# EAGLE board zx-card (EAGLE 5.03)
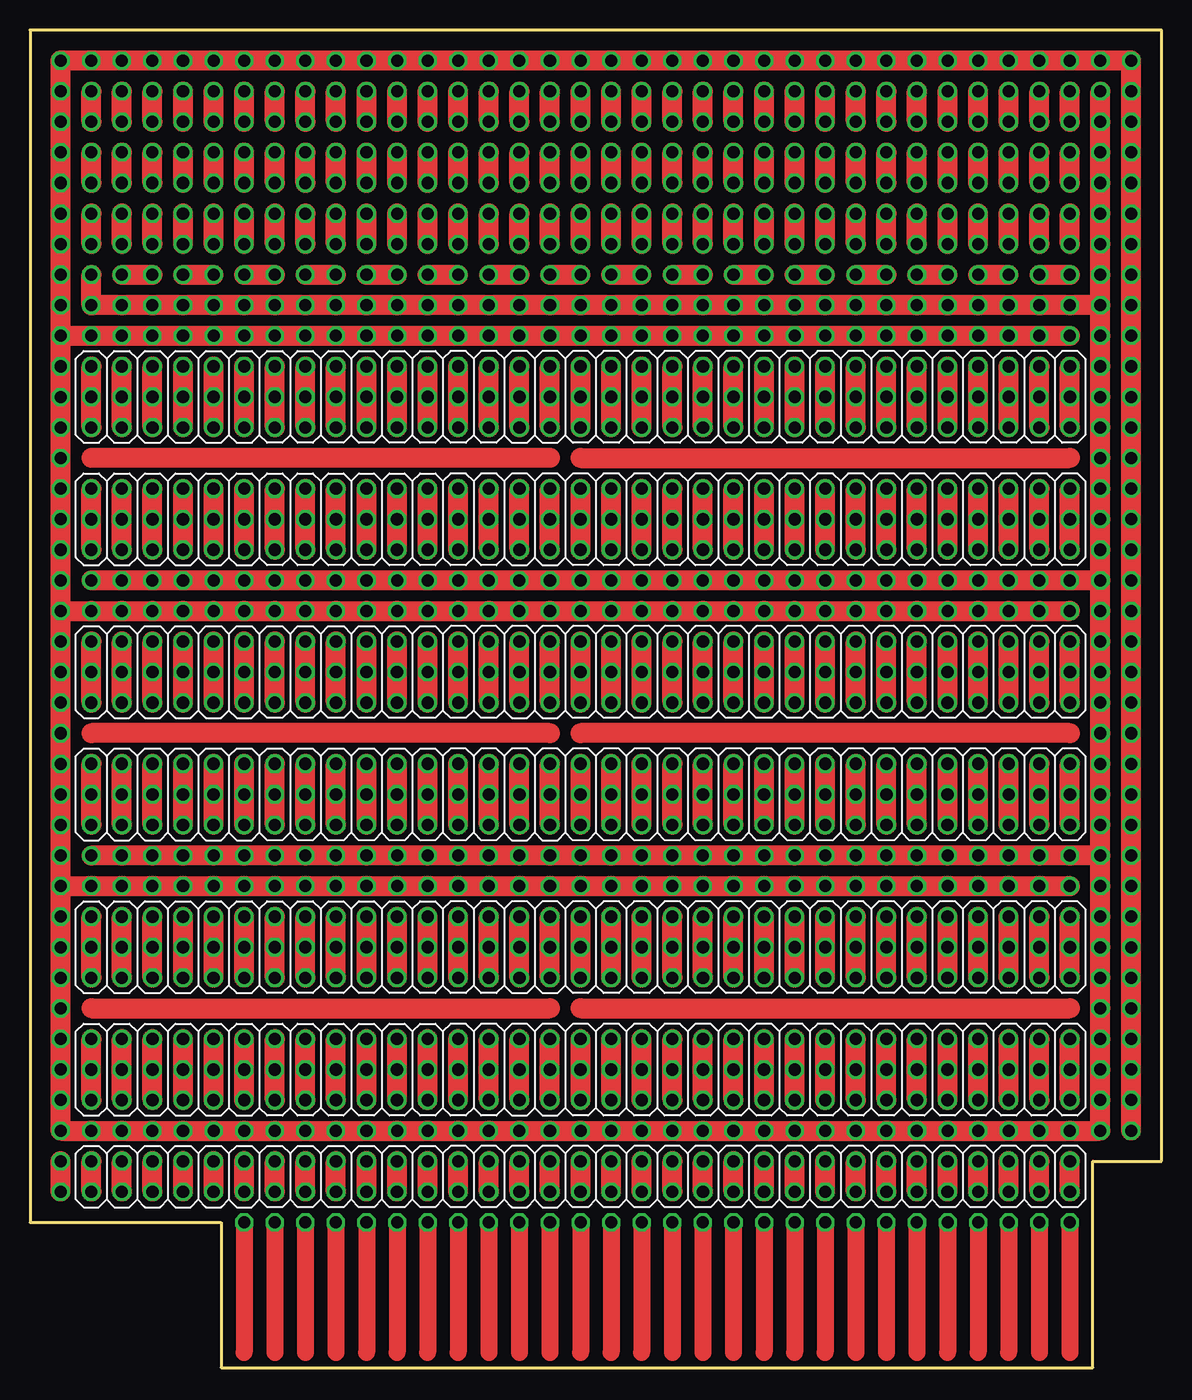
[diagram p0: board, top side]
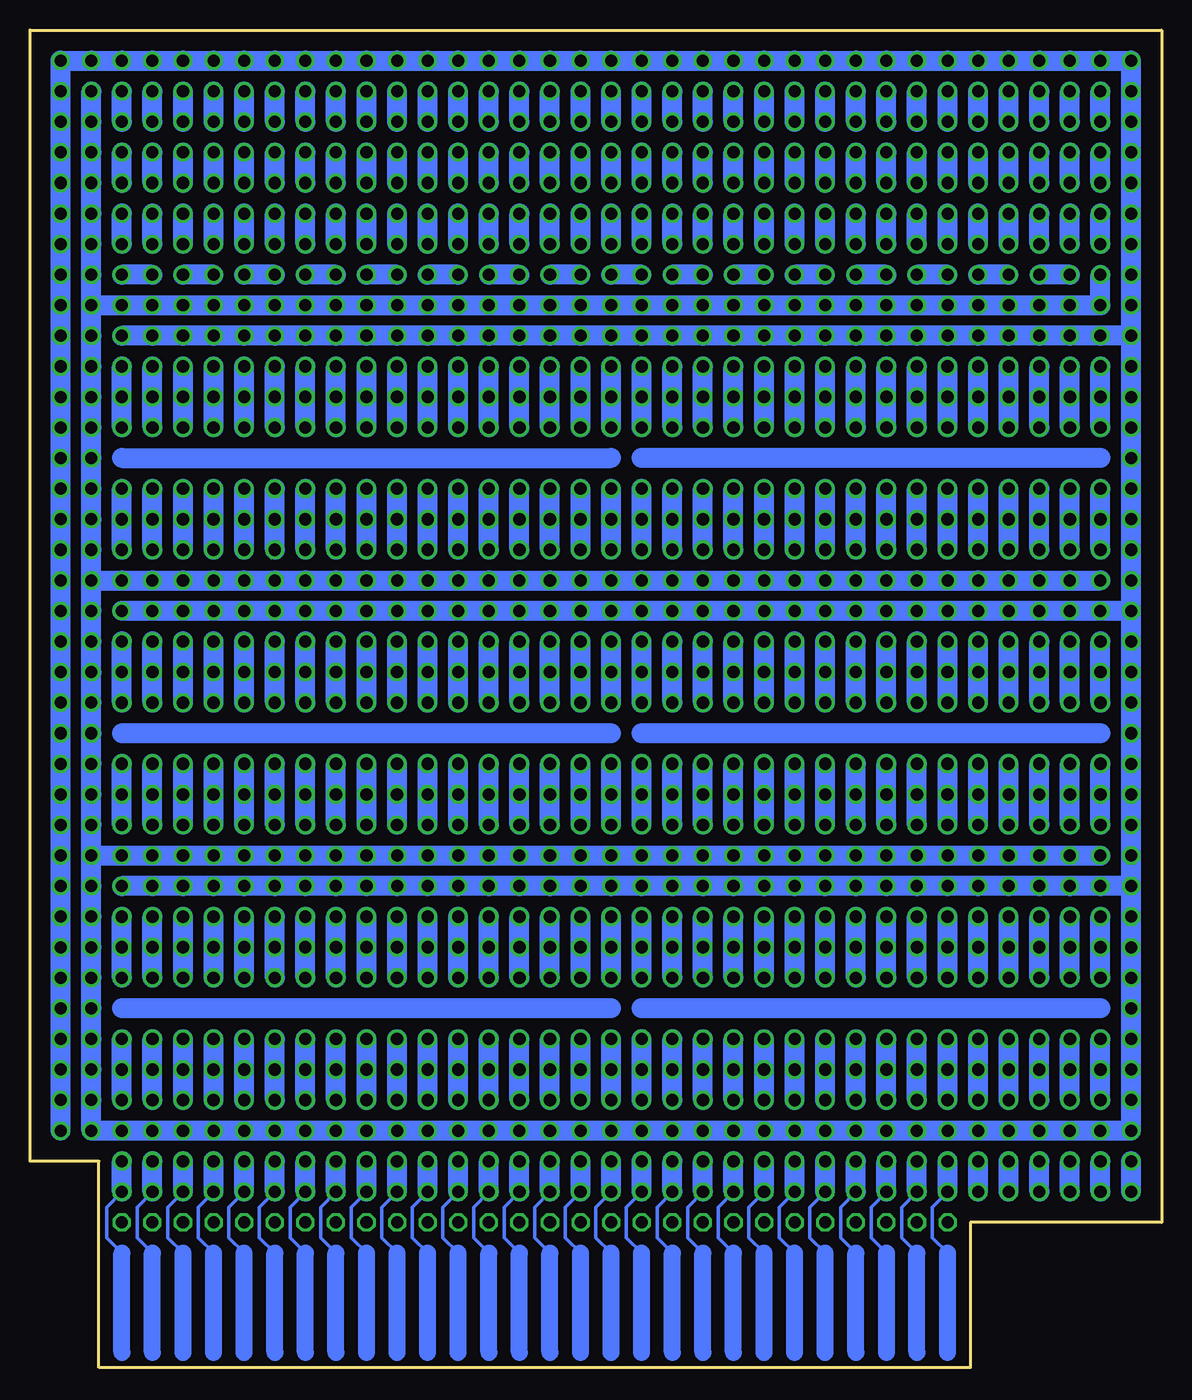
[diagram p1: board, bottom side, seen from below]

Size 93.98 x 111.12 mm. Coordinates in mm from the lower left corner, seen from the top.
Outline: 93.98,111.12 0,111.12 0,12.06 15.88,12.06 15.88,0 88.27,0 88.27,17.14 93.98,17.14 93.98,111.12
Copper layers (1*16): Top 0.035mm / dielectric 1.5mm / Bottom 0.035mm
Design rules "default": minimum track width 10mil, minimum drill 24mil, track to track 8mil, track to pad 8mil, pad to pad 8mil, via to via 8mil, smd to smd 8mil, copper to edge 40mil, drill to drill 8mil, minimum pad ring 10mil, minimum via ring 8mil, stop-mask expansion 4mil, vias tented up to drill 0mil, thermal gap 10mil

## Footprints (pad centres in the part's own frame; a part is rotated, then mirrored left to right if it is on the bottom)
2X30 = drill 1.016 octagon: 1 -38.1,-1.27; 2 -38.1,1.27; 3 -35.56,-1.27; 4 -35.56,1.27; 5 -33.02,-1.27; 6 -33.02,1.27; 7 -30.48,-1.27; 8 -30.48,1.27; 9 -27.94,-1.27; 10 -27.94,1.27; 11 -25.4,-1.27; 12 -25.4,1.27; 13 -22.86,-1.27; 14 -22.86,1.27; 15 -20.32,-1.27; 16 -20.32,1.27; 17 -17.78,-1.27; 18 -17.78,1.27; 19 -15.24,-1.27; 20 -15.24,1.27; 21 -12.7,-1.27; 22 -12.7,1.27; 23 -10.16,-1.27; 24 -10.16,1.27; 25 -7.62,-1.27; 26 -7.62,1.27; 27 -5.08,-1.27; 28 -5.08,1.27; 29 -2.54,-1.27; 30 -2.54,1.27; 31 0,-1.27; 32 0,1.27; 33 2.54,-1.27; 34 2.54,1.27; 35 5.08,-1.27; 36 5.08,1.27; 37 7.62,-1.27; 38 7.62,1.27; 39 10.16,-1.27; 40 10.16,1.27; 41 12.7,-1.27; 42 12.7,1.27; 43 15.24,-1.27; 44 15.24,1.27; 45 17.78,-1.27; 46 17.78,1.27; 47 20.32,-1.27; 48 20.32,1.27; 49 22.86,-1.27; 50 22.86,1.27; 51 25.4,-1.27; 52 25.4,1.27; 53 27.94,-1.27; 54 27.94,1.27; 55 30.48,-1.27; 56 30.48,1.27; 57 33.02,-1.27; 58 33.02,1.27; 59 35.56,-1.27; 60 35.56,1.27; 61 38.1,1.27; 62 38.1,-1.27; 63 40.64,1.27; 64 40.64,-1.27; 65 43.18,1.27; 66 43.18,-1.27
2X30' = drill 1.016 octagon: 1 -38.1,-1.27; 2 -38.1,3.81; 3 -35.56,-1.27; 4 -35.56,3.81; 5 -33.02,-1.27; 6 -33.02,3.81; 7 -30.48,-1.27; 8 -30.48,3.81; 9 -27.94,-1.27; 10 -27.94,3.81; 11 -25.4,-1.27; 12 -25.4,3.81; 13 -22.86,-1.27; 14 -22.86,3.81; 15 -20.32,-1.27; 16 -20.32,3.81; 17 -17.78,-1.27; 18 -17.78,3.81; 19 -15.24,-1.27; 20 -15.24,3.81; 21 -12.7,-1.27; 22 -12.7,3.81; 23 -10.16,-1.27; 24 -10.16,3.81; 25 -7.62,-1.27; 26 -7.62,3.81; 27 -5.08,-1.27; 28 -5.08,3.81; 29 -2.54,-1.27; 30 -2.54,3.81; 31 0,-1.27; 32 0,3.81; 33 2.54,-1.27; 34 2.54,3.81; 35 5.08,-1.27; 36 5.08,3.81; 37 7.62,-1.27; 38 7.62,3.81; 39 10.16,-1.27; 40 10.16,3.81; 41 12.7,-1.27; 42 12.7,3.81; 43 15.24,-1.27; 44 15.24,3.81; 45 17.78,-1.27; 46 17.78,3.81; 47 20.32,-1.27; 48 20.32,3.81; 49 22.86,-1.27; 50 22.86,3.81; 51 25.4,-1.27; 52 25.4,3.81; 53 27.94,-1.27; 54 27.94,3.81; 55 30.48,-1.27; 56 30.48,3.81; 57 33.02,-1.27; 58 33.02,3.81; 59 35.56,-1.27; 60 35.56,3.81; 61 38.1,3.81; 62 38.1,-1.27; 63 40.64,3.81; 64 40.64,-1.27; 65 43.18,3.81; 66 43.18,-1.27; 67 -38.1,1.27; 68 -35.56,1.27; 69 -33.02,1.27; 70 -30.48,1.27; 71 -27.94,1.27; 72 -25.4,1.27; 73 -22.86,1.27; 74 -20.32,1.27; 75 -17.78,1.27; 76 -15.24,1.27; 77 -12.7,1.27; 78 -10.16,1.27; 79 -7.62,1.27; 80 -5.08,1.27; 81 -2.54,1.27; 82 0,1.27; 83 2.54,1.27; 84 5.08,1.27; 85 7.62,1.27; 86 10.16,1.27; 87 12.7,1.27; 88 15.24,1.27; 89 17.78,1.27; 90 20.32,1.27; 91 22.86,1.27; 92 25.4,1.27; 93 27.94,1.27; 94 30.48,1.27; 95 33.02,1.27; 96 35.56,1.27; 97 38.1,1.27; 98 40.64,1.27; 99 43.18,1.27

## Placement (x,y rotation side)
E$5  [2X30]  43.18,15.88 0 top
E$6  [2X30']  43.18,23.5 0 top
E$7  [2X30']  43.18,33.66 0 top
E$8  [2X30']  43.18,46.36 0 top
E$9  [2X30']  43.18,56.52 0 top
E$10  [2X30']  43.18,69.22 0 top
E$11  [2X30']  43.18,79.38 0 top

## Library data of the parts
E$5 = pinhead-2x33
E$6-E$11 = pinhead-3x33

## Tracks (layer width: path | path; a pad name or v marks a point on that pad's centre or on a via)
S$1
  Bottom 1.676: 86.36,22.23 86.36,27.3 | 83.82,22.23 83.82,27.3 | 81.28,22.23 81.28,27.3 | 78.74,22.23 78.74,27.3 | 76.2,22.23 76.2,27.3 | 73.66,22.23 73.66,27.3 | 71.12,22.23 71.12,27.3 | 68.58,22.23 68.58,27.3 | 66.04,22.23 66.04,27.3 | 63.5,22.23 63.5,27.3 | 60.96,22.23 60.96,27.3 | 58.42,22.23 58.42,27.3 | 55.88,22.23 55.88,27.3 | 53.34,22.23 53.34,27.3 | 50.8,22.23 50.8,27.3 | 48.26,22.23 48.26,27.3 | 45.72,22.23 45.72,27.3 | 43.18,22.23 43.18,27.3 | 40.64,22.23 40.64,27.3 | 38.1,22.23 38.1,27.3 | 35.56,22.23 35.56,27.3 | 33.02,22.23 33.02,27.3 | 30.48,22.23 30.48,27.3 | 27.94,22.23 27.94,27.3 | 25.4,22.23 25.4,27.3 | 22.86,22.23 22.86,27.3 | 20.32,22.23 20.32,27.3 | 17.78,22.23 17.78,27.3 | 15.24,22.23 15.24,27.3 | 12.7,22.23 12.7,27.3 | 10.16,22.23 10.16,27.3 | 7.62,22.23 7.62,27.3 | 5.08,22.23 5.08,27.3
S$2
  Bottom 1.676: 5.08,75.56 43.18,75.56
S$3
  Top 1.676: 43.18,75.56 5.08,75.56
S$4
  Top 1.676: 45.72,75.56 86.36,75.56
S$5
  Bottom 1.676: 86.36,32.38 86.36,37.47 | 83.82,32.38 83.82,37.47 | 81.28,32.38 81.28,37.47 | 78.74,32.38 78.74,37.47 | 76.2,32.38 76.2,37.47 | 73.66,32.38 73.66,37.47 | 71.12,32.38 71.12,37.47 | 68.58,32.38 68.58,37.47 | 66.04,32.38 66.04,37.47 | 63.5,32.38 63.5,37.47 | 60.96,32.38 60.96,37.47 | 58.42,32.38 58.42,37.47 | 55.88,32.38 55.88,37.47 | 53.34,32.38 53.34,37.47 | 50.8,32.38 50.8,37.47 | 48.26,32.38 48.26,37.47 | 45.72,32.38 45.72,37.47 | 43.18,32.38 43.18,37.47 | 40.64,32.38 40.64,37.47 | 38.1,32.38 38.1,37.47 | 35.56,32.38 35.56,37.47 | 33.02,32.38 33.02,37.47 | 30.48,32.38 30.48,37.47 | 27.94,32.38 27.94,37.47 | 25.4,32.38 25.4,37.47 | 22.86,32.38 22.86,37.47 | 20.32,32.38 20.32,37.47 | 17.78,32.38 17.78,37.47 | 15.24,32.38 15.24,37.47 | 12.7,32.38 12.7,37.47 | 10.16,32.38 10.16,37.47 | 7.62,32.38 7.62,37.47 | 5.08,32.38 5.08,37.47
S$6
  Bottom 1.676: 86.36,45.09 86.36,50.16 | 83.82,45.09 83.82,50.16 | 81.28,45.09 81.28,50.16 | 78.74,45.09 78.74,50.16 | 76.2,45.09 76.2,50.16 | 73.66,45.09 73.66,50.16 | 71.12,45.09 71.12,50.16 | 68.58,45.09 68.58,50.16 | 66.04,45.09 66.04,50.16 | 63.5,45.09 63.5,50.16 | 60.96,45.09 60.96,50.16 | 58.42,45.09 58.42,50.16 | 55.88,45.09 55.88,50.16 | 53.34,45.09 53.34,50.16 | 50.8,45.09 50.8,50.16 | 48.26,45.09 48.26,50.16 | 45.72,45.09 45.72,50.16 | 43.18,45.09 43.18,50.16 | 40.64,45.09 40.64,50.16 | 38.1,45.09 38.1,50.16 | 35.56,45.09 35.56,50.16 | 33.02,45.09 33.02,50.16 | 30.48,45.09 30.48,50.16 | 27.94,45.09 27.94,50.16 | 25.4,45.09 25.4,50.16 | 22.86,45.09 22.86,50.16 | 20.32,45.09 20.32,50.16 | 17.78,45.09 17.78,50.16 | 15.24,45.09 15.24,50.16 | 12.7,45.09 12.7,50.16 | 10.16,45.09 10.16,50.16 | 7.62,45.09 7.62,50.16 | 5.08,45.09 5.08,50.16
S$7
  Bottom 1.676: 86.36,55.25 86.36,60.33 | 83.82,55.25 83.82,60.33 | 81.28,55.25 81.28,60.33 | 78.74,55.25 78.74,60.33 | 76.2,55.25 76.2,60.33 | 73.66,55.25 73.66,60.33 | 71.12,55.25 71.12,60.33 | 68.58,55.25 68.58,60.33 | 66.04,55.25 66.04,60.33 | 63.5,55.25 63.5,60.33 | 60.96,55.25 60.96,60.33 | 58.42,55.25 58.42,60.33 | 55.88,55.25 55.88,60.33 | 53.34,55.25 53.34,60.33 | 50.8,55.25 50.8,60.33 | 48.26,55.25 48.26,60.33 | 45.72,55.25 45.72,60.33 | 43.18,55.25 43.18,60.33 | 40.64,55.25 40.64,60.33 | 38.1,55.25 38.1,60.33 | 35.56,55.25 35.56,60.33 | 33.02,55.25 33.02,60.33 | 30.48,55.25 30.48,60.33 | 27.94,55.25 27.94,60.33 | 25.4,55.25 25.4,60.33 | 22.86,55.25 22.86,60.33 | 20.32,55.25 20.32,60.33 | 17.78,55.25 17.78,60.33 | 15.24,55.25 15.24,60.33 | 12.7,55.25 12.7,60.33 | 10.16,55.25 10.16,60.33 | 7.62,55.25 7.62,60.33 | 5.08,55.25 5.08,60.33
S$8
  Bottom 1.676: 86.36,67.95 86.36,73.03 | 83.82,67.95 83.82,73.03 | 81.28,67.95 81.28,73.03 | 78.74,67.95 78.74,73.03 | 76.2,67.95 76.2,73.03 | 73.66,67.95 73.66,73.03 | 71.12,67.95 71.12,73.03 | 68.58,67.95 68.58,73.03 | 66.04,67.95 66.04,73.03 | 63.5,67.95 63.5,73.03 | 60.96,67.95 60.96,73.03 | 58.42,67.95 58.42,73.03 | 55.88,67.95 55.88,73.03 | 53.34,67.95 53.34,73.03 | 50.8,67.95 50.8,73.03 | 48.26,67.95 48.26,73.03 | 45.72,67.95 45.72,73.03 | 43.18,67.95 43.18,73.03 | 40.64,67.95 40.64,73.03 | 38.1,67.95 38.1,73.03 | 35.56,67.95 35.56,73.03 | 33.02,67.95 33.02,73.03 | 30.48,67.95 30.48,73.03 | 27.94,67.95 27.94,73.03 | 25.4,67.95 25.4,73.03 | 22.86,67.95 22.86,73.03 | 20.32,67.95 20.32,73.03 | 17.78,67.95 17.78,73.03 | 15.24,67.95 15.24,73.03 | 12.7,67.95 12.7,73.03 | 10.16,67.95 10.16,73.03 | 7.62,67.95 7.62,73.03 | 5.08,67.95 5.08,73.03
S$9
  Bottom 1.676: 86.36,78.11 86.36,83.19 | 83.82,78.11 83.82,83.19 | 81.28,78.11 81.28,83.19 | 78.74,78.11 78.74,83.19 | 76.2,78.11 76.2,83.19 | 73.66,78.11 73.66,83.19 | 71.12,78.11 71.12,83.19 | 68.58,78.11 68.58,83.19 | 66.04,78.11 66.04,83.19 | 63.5,78.11 63.5,83.19 | 60.96,78.11 60.96,83.19 | 58.42,78.11 58.42,83.19 | 55.88,78.11 55.88,83.19 | 53.34,78.11 53.34,83.19 | 50.8,78.11 50.8,83.19 | 48.26,78.11 48.26,83.19 | 45.72,78.11 45.72,83.19 | 43.18,78.11 43.18,83.19 | 40.64,78.11 40.64,83.19 | 38.1,78.11 38.1,83.19 | 35.56,78.11 35.56,83.19 | 33.02,78.11 33.02,83.19 | 30.48,78.11 30.48,83.19 | 27.94,78.11 27.94,83.19 | 25.4,78.11 25.4,83.19 | 22.86,78.11 22.86,83.19 | 20.32,78.11 20.32,83.19 | 17.78,78.11 17.78,83.19 | 15.24,78.11 15.24,83.19 | 12.7,78.11 12.7,83.19 | 10.16,78.11 10.16,83.19 | 7.62,78.11 7.62,83.19 | 5.08,78.11 5.08,83.19
S$10
  Bottom 1.676: 86.36,75.56 45.72,75.56
S$11
  Bottom 1.676: 86.36,52.7 45.72,52.7
S$12
  Bottom 1.676: 43.18,52.7 5.08,52.7
S$13
  Bottom 1.676: 5.08,29.85 43.18,29.85
S$14
  Bottom 1.676: 45.72,29.85 86.36,29.85
S$15
  Top 1.676: 86.36,22.23 86.36,27.3 | 83.82,22.23 83.82,27.3 | 81.28,22.23 81.28,27.3 | 78.74,22.23 78.74,27.3 | 76.2,22.23 76.2,27.3 | 73.66,22.23 73.66,27.3 | 71.12,22.23 71.12,27.3 | 68.58,22.23 68.58,27.3 | 66.04,22.23 66.04,27.3 | 63.5,22.23 63.5,27.3 | 60.96,22.23 60.96,27.3 | 58.42,22.23 58.42,27.3 | 55.88,22.23 55.88,27.3 | 53.34,22.23 53.34,27.3 | 50.8,22.23 50.8,27.3 | 48.26,22.23 48.26,27.3 | 45.72,22.23 45.72,27.3 | 43.18,22.23 43.18,27.3 | 40.64,22.23 40.64,27.3 | 38.1,22.23 38.1,27.3 | 35.56,22.23 35.56,27.3 | 33.02,22.23 33.02,27.3 | 30.48,22.23 30.48,27.3 | 27.94,22.23 27.94,27.3 | 25.4,22.23 25.4,27.3 | 22.86,22.23 22.86,27.3 | 20.32,22.23 20.32,27.3 | 17.78,22.23 17.78,27.3 | 15.24,22.23 15.24,27.3 | 12.7,22.23 12.7,27.3 | 10.16,22.23 10.16,27.3 | 7.62,22.23 7.62,27.3 | 5.08,22.23 5.08,27.3
S$17  (via drill 1 pad 1.42)
  Top 1.676: v88.9,42.55 v88.9,40.01 v88.9,37.47 v88.9,34.93 v88.9,32.38 v88.9,29.85 v88.9,27.3 v88.9,24.77 v88.9,22.23 v88.9,19.69 v86.36,19.69 v83.82,19.69 v81.28,19.69 v78.74,19.69 v76.2,19.69 v73.66,19.69 v71.12,19.69 v68.58,19.69 v66.04,19.69 v63.5,19.69 v60.96,19.69 v58.42,19.69 v55.88,19.69 v53.34,19.69 v50.8,19.69 v48.26,19.69 v45.72,19.69 v43.18,19.69 v40.64,19.69 v38.1,19.69 v35.56,19.69 v33.02,19.69 v30.48,19.69 v27.94,19.69 v25.4,19.69 v22.86,19.69 v20.32,19.69 v17.78,19.69 v15.24,19.69 v12.7,19.69 v10.16,19.69 v7.62,19.69 v5.08,19.69 v2.54,19.69 v2.54,22.23 v2.54,24.77 v2.54,27.3 v2.54,29.85 v2.54,32.38 v2.54,34.93 v2.54,37.47 v2.54,40.01 | v2.54,40.01 v5.08,40.01 v7.62,40.01 v10.16,40.01 v12.7,40.01 v15.24,40.01 v17.78,40.01 v20.32,40.01 v22.86,40.01 v25.4,40.01 v27.94,40.01 v30.48,40.01 v33.02,40.01 v35.56,40.01 v38.1,40.01 v40.64,40.01 v43.18,40.01 v45.72,40.01 v48.26,40.01 v50.8,40.01 v53.34,40.01 v55.88,40.01 v58.42,40.01 v60.96,40.01 v63.5,40.01 v66.04,40.01 v68.58,40.01 v71.12,40.01 v73.66,40.01 v76.2,40.01 v78.74,40.01 v81.28,40.01 v83.82,40.01 v86.36,40.01 | v88.9,42.55 v86.36,42.55 v83.82,42.55 v81.28,42.55 v78.74,42.55 v76.2,42.55 v73.66,42.55 v71.12,42.55 v68.58,42.55 v66.04,42.55 v63.5,42.55 v60.96,42.55 v58.42,42.55 v55.88,42.55 v53.34,42.55 v50.8,42.55 v48.26,42.55 v45.72,42.55 v43.18,42.55 v40.64,42.55 v38.1,42.55 v35.56,42.55 v33.02,42.55 v30.48,42.55 v27.94,42.55 v25.4,42.55 v22.86,42.55 v20.32,42.55 v17.78,42.55 v15.24,42.55 v12.7,42.55 v10.16,42.55 v7.62,42.55 v5.08,42.55
  Top 1.676: v2.54,40.01 v2.54,42.55 v2.54,45.09 v2.54,47.62 v2.54,50.16 v2.54,52.7 v2.54,55.25 v2.54,57.79 v2.54,60.33 v2.54,62.87 | v2.54,62.87 v5.08,62.87 v7.62,62.87 v10.16,62.87 v12.7,62.87 v15.24,62.87 v17.78,62.87 v20.32,62.87 v22.86,62.87 v25.4,62.87 v27.94,62.87 v30.48,62.87 v33.02,62.87 v35.56,62.87 v38.1,62.87 v40.64,62.87 v43.18,62.87 v45.72,62.87 v48.26,62.87 v50.8,62.87 v53.34,62.87 v55.88,62.87 v58.42,62.87 v60.96,62.87 v63.5,62.87 v66.04,62.87 v68.58,62.87 v71.12,62.87 v73.66,62.87 v76.2,62.87 v78.74,62.87 v81.28,62.87 v83.82,62.87 v86.36,62.87 | v88.9,42.55 v88.9,45.09 v88.9,47.62 v88.9,50.16 v88.9,52.7 v88.9,55.25 v88.9,57.79 v88.9,60.33 v88.9,62.87 v88.9,65.41 | v88.9,65.41 v86.36,65.41 v83.82,65.41 v81.28,65.41 v78.74,65.41 v76.2,65.41 v73.66,65.41 v71.12,65.41 v68.58,65.41 v66.04,65.41 v63.5,65.41 v60.96,65.41 v58.42,65.41 v55.88,65.41 v53.34,65.41 v50.8,65.41 v48.26,65.41 v45.72,65.41 v43.18,65.41 v40.64,65.41 v38.1,65.41 v35.56,65.41 v33.02,65.41 v30.48,65.41 v27.94,65.41 v25.4,65.41 v22.86,65.41 v20.32,65.41 v17.78,65.41 v15.24,65.41 v12.7,65.41 v10.16,65.41 v7.62,65.41 v5.08,65.41 | v2.54,62.87 v2.54,65.41 v2.54,67.95 v2.54,70.48 v2.54,73.03 v2.54,75.56 v2.54,78.11 v2.54,80.64 v2.54,83.19 v2.54,85.72 | v2.54,85.72 v5.08,85.72 v7.62,85.72 v10.16,85.72 v12.7,85.72 v15.24,85.72 v17.78,85.72 v20.32,85.72 v22.86,85.72 v25.4,85.72 v27.94,85.72 v30.48,85.72 v33.02,85.72 v35.56,85.72 v38.1,85.72 v40.64,85.72 v43.18,85.72 v45.72,85.72 v48.26,85.72 v50.8,85.72 v53.34,85.72 v55.88,85.72 v58.42,85.72 v60.96,85.72 v63.5,85.72 v66.04,85.72 v68.58,85.72 v71.12,85.72 v73.66,85.72 v76.2,85.72 v78.74,85.72 v81.28,85.72 v83.82,85.72 v86.36,85.72
  Top 1.676: v88.9,65.41 v88.9,67.95 v88.9,70.48 v88.9,73.03 v88.9,75.56 v88.9,78.11 v88.9,80.64 v88.9,83.19 v88.9,85.72 v88.9,88.27 | v88.9,88.27 v86.36,88.27 v83.82,88.27 v81.28,88.27 v78.74,88.27 v76.2,88.27 v73.66,88.27 v71.12,88.27 v68.58,88.27 v66.04,88.27 v63.5,88.27 v60.96,88.27 v58.42,88.27 v55.88,88.27 v53.34,88.27 v50.8,88.27 v48.26,88.27 v45.72,88.27 v43.18,88.27 v40.64,88.27 v38.1,88.27 v35.56,88.27 v33.02,88.27 v30.48,88.27 v27.94,88.27 v25.4,88.27 v22.86,88.27 v20.32,88.27 v17.78,88.27 v15.24,88.27 v12.7,88.27 v10.16,88.27 v7.62,88.27 v5.08,88.27 v5.08,90.81 | v91.44,19.69 v91.44,22.23 v91.44,24.77 v91.44,27.3 v91.44,29.85 v91.44,32.38 v91.44,34.93 v91.44,37.47 v91.44,40.01 v91.44,42.55 v91.44,45.09 v91.44,47.62 v91.44,50.16 v91.44,52.7 v91.44,55.25 v91.44,57.79 v91.44,60.33 v91.44,62.87 v91.44,65.41 v91.44,67.95 v91.44,70.48 v91.44,73.03 v91.44,75.56 v91.44,78.11 v91.44,80.64 v91.44,83.19 v91.44,85.72 v91.44,88.27 v91.44,90.81 v91.44,93.34 v91.44,95.89 v91.44,98.42 v91.44,100.97 v91.44,103.5 v91.44,106.05 v91.44,108.59 v88.9,108.59 v86.36,108.59 v83.82,108.59 v81.28,108.59 v78.74,108.59 v76.2,108.59 v73.66,108.59 v71.12,108.59 v68.58,108.59 v66.04,108.59 v63.5,108.59 v60.96,108.59 v58.42,108.59 v55.88,108.59 v53.34,108.59 v50.8,108.59 v48.26,108.59 v45.72,108.59 v43.18,108.59 v40.64,108.59 v38.1,108.59 v35.56,108.59 v33.02,108.59 v30.48,108.59 v27.94,108.59 v25.4,108.59 v22.86,108.59 v20.32,108.59 v17.78,108.59 v15.24,108.59 v12.7,108.59 v10.16,108.59 v7.62,108.59 v5.08,108.59 v2.54,108.59 v2.54,106.05 v2.54,103.5 v2.54,100.97 v2.54,98.42 v2.54,95.89 v2.54,93.34 v2.54,90.81 v2.54,88.27 v2.54,85.72
  Top 1.676: v88.9,88.27 v88.9,90.81 v88.9,93.34 v88.9,95.89 v88.9,98.42 v88.9,100.97 v88.9,103.5 v88.9,106.05
  Bottom 1.676: v88.9,42.55 v88.9,40.01 v88.9,37.47 v88.9,34.93 v88.9,32.38 v88.9,29.85 v88.9,27.3 v88.9,24.77 v88.9,22.23 v88.9,19.69 v86.36,19.69 v83.82,19.69 v81.28,19.69 v78.74,19.69 v76.2,19.69 v73.66,19.69 v71.12,19.69 v68.58,19.69 v66.04,19.69 v63.5,19.69 v60.96,19.69 v58.42,19.69 v55.88,19.69 v53.34,19.69 v50.8,19.69 v48.26,19.69 v45.72,19.69 v43.18,19.69 v40.64,19.69 v38.1,19.69 v35.56,19.69 v33.02,19.69 v30.48,19.69 v27.94,19.69 v25.4,19.69 v22.86,19.69 v20.32,19.69 v17.78,19.69 v15.24,19.69 v12.7,19.69 v10.16,19.69 v7.62,19.69 v5.08,19.69 v2.54,19.69 v2.54,22.23 v2.54,24.77 v2.54,27.3 v2.54,29.85 v2.54,32.38 v2.54,34.93 v2.54,37.47 v2.54,40.01 | v2.54,40.01 v5.08,40.01 v7.62,40.01 v10.16,40.01 v12.7,40.01 v15.24,40.01 v17.78,40.01 v20.32,40.01 v22.86,40.01 v25.4,40.01 v27.94,40.01 v30.48,40.01 v33.02,40.01 v35.56,40.01 v38.1,40.01 v40.64,40.01 v43.18,40.01 v45.72,40.01 v48.26,40.01 v50.8,40.01 v53.34,40.01 v55.88,40.01 v58.42,40.01 v60.96,40.01 v63.5,40.01 v66.04,40.01 v68.58,40.01 v71.12,40.01 v73.66,40.01 v76.2,40.01 v78.74,40.01 v81.28,40.01 v83.82,40.01 v86.36,40.01 | v88.9,42.55 v86.36,42.55 v83.82,42.55 v81.28,42.55 v78.74,42.55 v76.2,42.55 v73.66,42.55 v71.12,42.55 v68.58,42.55 v66.04,42.55 v63.5,42.55 v60.96,42.55 v58.42,42.55 v55.88,42.55 v53.34,42.55 v50.8,42.55 v48.26,42.55 v45.72,42.55 v43.18,42.55 v40.64,42.55 v38.1,42.55 v35.56,42.55 v33.02,42.55 v30.48,42.55 v27.94,42.55 v25.4,42.55 v22.86,42.55 v20.32,42.55 v17.78,42.55 v15.24,42.55 v12.7,42.55 v10.16,42.55 v7.62,42.55 v5.08,42.55
  Bottom 1.676: v2.54,40.01 v2.54,42.55 v2.54,45.09 v2.54,47.62 v2.54,50.16 v2.54,52.7 v2.54,55.25 v2.54,57.79 v2.54,60.33 v2.54,62.87 | v2.54,62.87 v5.08,62.87 v7.62,62.87 v10.16,62.87 v12.7,62.87 v15.24,62.87 v17.78,62.87 v20.32,62.87 v22.86,62.87 v25.4,62.87 v27.94,62.87 v30.48,62.87 v33.02,62.87 v35.56,62.87 v38.1,62.87 v40.64,62.87 v43.18,62.87 v45.72,62.87 v48.26,62.87 v50.8,62.87 v53.34,62.87 v55.88,62.87 v58.42,62.87 v60.96,62.87 v63.5,62.87 v66.04,62.87 v68.58,62.87 v71.12,62.87 v73.66,62.87 v76.2,62.87 v78.74,62.87 v81.28,62.87 v83.82,62.87 v86.36,62.87 | v88.9,42.55 v88.9,45.09 v88.9,47.62 v88.9,50.16 v88.9,52.7 v88.9,55.25 v88.9,57.79 v88.9,60.33 v88.9,62.87 v88.9,65.41 | v88.9,65.41 v86.36,65.41 v83.82,65.41 v81.28,65.41 v78.74,65.41 v76.2,65.41 v73.66,65.41 v71.12,65.41 v68.58,65.41 v66.04,65.41 v63.5,65.41 v60.96,65.41 v58.42,65.41 v55.88,65.41 v53.34,65.41 v50.8,65.41 v48.26,65.41 v45.72,65.41 v43.18,65.41 v40.64,65.41 v38.1,65.41 v35.56,65.41 v33.02,65.41 v30.48,65.41 v27.94,65.41 v25.4,65.41 v22.86,65.41 v20.32,65.41 v17.78,65.41 v15.24,65.41 v12.7,65.41 v10.16,65.41 v7.62,65.41 v5.08,65.41 | v2.54,62.87 v2.54,65.41 v2.54,67.95 v2.54,70.48 v2.54,73.03 v2.54,75.56 v2.54,78.11 v2.54,80.64 v2.54,83.19 v2.54,85.72 | v2.54,85.72 v5.08,85.72 v7.62,85.72 v10.16,85.72 v12.7,85.72 v15.24,85.72 v17.78,85.72 v20.32,85.72 v22.86,85.72 v25.4,85.72 v27.94,85.72 v30.48,85.72 v33.02,85.72 v35.56,85.72 v38.1,85.72 v40.64,85.72 v43.18,85.72 v45.72,85.72 v48.26,85.72 v50.8,85.72 v53.34,85.72 v55.88,85.72 v58.42,85.72 v60.96,85.72 v63.5,85.72 v66.04,85.72 v68.58,85.72 v71.12,85.72 v73.66,85.72 v76.2,85.72 v78.74,85.72 v81.28,85.72 v83.82,85.72 v86.36,85.72
  Bottom 1.676: v88.9,65.41 v88.9,67.95 v88.9,70.48 v88.9,73.03 v88.9,75.56 v88.9,78.11 v88.9,80.64 v88.9,83.19 v88.9,85.72 v88.9,88.27 | v88.9,88.27 v86.36,88.27 v83.82,88.27 v81.28,88.27 v78.74,88.27 v76.2,88.27 v73.66,88.27 v71.12,88.27 v68.58,88.27 v66.04,88.27 v63.5,88.27 v60.96,88.27 v58.42,88.27 v55.88,88.27 v53.34,88.27 v50.8,88.27 v48.26,88.27 v45.72,88.27 v43.18,88.27 v40.64,88.27 v38.1,88.27 v35.56,88.27 v33.02,88.27 v30.48,88.27 v27.94,88.27 v25.4,88.27 v22.86,88.27 v20.32,88.27 v17.78,88.27 v15.24,88.27 v12.7,88.27 v10.16,88.27 v7.62,88.27 v5.08,88.27 v5.08,90.81 | v91.44,19.69 v91.44,22.23 v91.44,24.77 v91.44,27.3 v91.44,29.85 v91.44,32.38 v91.44,34.93 v91.44,37.47 v91.44,40.01 v91.44,42.55 v91.44,45.09 v91.44,47.62 v91.44,50.16 v91.44,52.7 v91.44,55.25 v91.44,57.79 v91.44,60.33 v91.44,62.87 v91.44,65.41 v91.44,67.95 v91.44,70.48 v91.44,73.03 v91.44,75.56 v91.44,78.11 v91.44,80.64 v91.44,83.19 v91.44,85.72 v91.44,88.27 v91.44,90.81 v91.44,93.34 v91.44,95.89 v91.44,98.42 v91.44,100.97 v91.44,103.5 v91.44,106.05 v91.44,108.59 v88.9,108.59 v86.36,108.59 v83.82,108.59 v81.28,108.59 v78.74,108.59 v76.2,108.59 v73.66,108.59 v71.12,108.59 v68.58,108.59 v66.04,108.59 v63.5,108.59 v60.96,108.59 v58.42,108.59 v55.88,108.59 v53.34,108.59 v50.8,108.59 v48.26,108.59 v45.72,108.59 v43.18,108.59 v40.64,108.59 v38.1,108.59 v35.56,108.59 v33.02,108.59 v30.48,108.59 v27.94,108.59 v25.4,108.59 v22.86,108.59 v20.32,108.59 v17.78,108.59 v15.24,108.59 v12.7,108.59 v10.16,108.59 v7.62,108.59 v5.08,108.59 v2.54,108.59 v2.54,106.05 v2.54,103.5 v2.54,100.97 v2.54,98.42 v2.54,95.89 v2.54,93.34 v2.54,90.81 v2.54,88.27 v2.54,85.72
  Bottom 1.676: v88.9,88.27 v88.9,90.81 v88.9,93.34 v88.9,95.89 v88.9,98.42 v88.9,100.97 v88.9,103.5 v88.9,106.05
S$18
  Top 1.676: 86.36,52.7 45.72,52.7
S$19
  Top 1.676: 86.36,32.38 86.36,37.47 | 83.82,32.38 83.82,37.47 | 81.28,32.38 81.28,37.47 | 78.74,32.38 78.74,37.47 | 76.2,32.38 76.2,37.47 | 73.66,32.38 73.66,37.47 | 71.12,32.38 71.12,37.47 | 68.58,32.38 68.58,37.47 | 66.04,32.38 66.04,37.47 | 63.5,32.38 63.5,37.47 | 60.96,32.38 60.96,37.47 | 58.42,32.38 58.42,37.47 | 55.88,32.38 55.88,37.47 | 53.34,32.38 53.34,37.47 | 50.8,32.38 50.8,37.47 | 48.26,32.38 48.26,37.47 | 45.72,32.38 45.72,37.47 | 43.18,32.38 43.18,37.47 | 40.64,32.38 40.64,37.47 | 38.1,32.38 38.1,37.47 | 35.56,32.38 35.56,37.47 | 33.02,32.38 33.02,37.47 | 30.48,32.38 30.48,37.47 | 27.94,32.38 27.94,37.47 | 25.4,32.38 25.4,37.47 | 22.86,32.38 22.86,37.47 | 20.32,32.38 20.32,37.47 | 17.78,32.38 17.78,37.47 | 15.24,32.38 15.24,37.47 | 12.7,32.38 12.7,37.47 | 10.16,32.38 10.16,37.47 | 7.62,32.38 7.62,37.47 | 5.08,32.38 5.08,37.47
S$20
  Top 1.676: 86.36,45.09 86.36,50.16 | 83.82,45.09 83.82,50.16 | 81.28,45.09 81.28,50.16 | 78.74,45.09 78.74,50.16 | 76.2,45.09 76.2,50.16 | 73.66,45.09 73.66,50.16 | 71.12,45.09 71.12,50.16 | 68.58,45.09 68.58,50.16 | 66.04,45.09 66.04,50.16 | 63.5,45.09 63.5,50.16 | 60.96,45.09 60.96,50.16 | 58.42,45.09 58.42,50.16 | 55.88,45.09 55.88,50.16 | 53.34,45.09 53.34,50.16 | 50.8,45.09 50.8,50.16 | 48.26,45.09 48.26,50.16 | 45.72,45.09 45.72,50.16 | 43.18,45.09 43.18,50.16 | 40.64,45.09 40.64,50.16 | 38.1,45.09 38.1,50.16 | 35.56,45.09 35.56,50.16 | 33.02,45.09 33.02,50.16 | 30.48,45.09 30.48,50.16 | 27.94,45.09 27.94,50.16 | 25.4,45.09 25.4,50.16 | 22.86,45.09 22.86,50.16 | 20.32,45.09 20.32,50.16 | 17.78,45.09 17.78,50.16 | 15.24,45.09 15.24,50.16 | 12.7,45.09 12.7,50.16 | 10.16,45.09 10.16,50.16 | 7.62,45.09 7.62,50.16 | 5.08,45.09 5.08,50.16
S$21
  Top 1.676: 86.36,55.25 86.36,60.33 | 83.82,55.25 83.82,60.33 | 81.28,55.25 81.28,60.33 | 78.74,55.25 78.74,60.33 | 76.2,55.25 76.2,60.33 | 73.66,55.25 73.66,60.33 | 71.12,55.25 71.12,60.33 | 68.58,55.25 68.58,60.33 | 66.04,55.25 66.04,60.33 | 63.5,55.25 63.5,60.33 | 60.96,55.25 60.96,60.33 | 58.42,55.25 58.42,60.33 | 55.88,55.25 55.88,60.33 | 53.34,55.25 53.34,60.33 | 50.8,55.25 50.8,60.33 | 48.26,55.25 48.26,60.33 | 45.72,55.25 45.72,60.33 | 43.18,55.25 43.18,60.33 | 40.64,55.25 40.64,60.33 | 38.1,55.25 38.1,60.33 | 35.56,55.25 35.56,60.33 | 33.02,55.25 33.02,60.33 | 30.48,55.25 30.48,60.33 | 27.94,55.25 27.94,60.33 | 25.4,55.25 25.4,60.33 | 22.86,55.25 22.86,60.33 | 20.32,55.25 20.32,60.33 | 17.78,55.25 17.78,60.33 | 15.24,55.25 15.24,60.33 | 12.7,55.25 12.7,60.33 | 10.16,55.25 10.16,60.33 | 7.62,55.25 7.62,60.33 | 5.08,55.25 5.08,60.33
S$22
  Top 1.676: 86.36,67.95 86.36,73.03 | 83.82,67.95 83.82,73.03 | 81.28,67.95 81.28,73.03 | 78.74,67.95 78.74,73.03 | 76.2,67.95 76.2,73.03 | 73.66,67.95 73.66,73.03 | 71.12,67.95 71.12,73.03 | 68.58,67.95 68.58,73.03 | 66.04,67.95 66.04,73.03 | 63.5,67.95 63.5,73.03 | 60.96,67.95 60.96,73.03 | 58.42,67.95 58.42,73.03 | 55.88,67.95 55.88,73.03 | 53.34,67.95 53.34,73.03 | 50.8,67.95 50.8,73.03 | 48.26,67.95 48.26,73.03 | 45.72,67.95 45.72,73.03 | 43.18,67.95 43.18,73.03 | 40.64,67.95 40.64,73.03 | 38.1,67.95 38.1,73.03 | 35.56,67.95 35.56,73.03 | 33.02,67.95 33.02,73.03 | 30.48,67.95 30.48,73.03 | 27.94,67.95 27.94,73.03 | 25.4,67.95 25.4,73.03 | 22.86,67.95 22.86,73.03 | 20.32,67.95 20.32,73.03 | 17.78,67.95 17.78,73.03 | 15.24,67.95 15.24,73.03 | 12.7,67.95 12.7,73.03 | 10.16,67.95 10.16,73.03 | 7.62,67.95 7.62,73.03 | 5.08,67.95 5.08,73.03
S$23
  Top 1.676: 86.36,78.11 86.36,83.19 | 83.82,78.11 83.82,83.19 | 81.28,78.11 81.28,83.19 | 78.74,78.11 78.74,83.19 | 76.2,78.11 76.2,83.19 | 73.66,78.11 73.66,83.19 | 71.12,78.11 71.12,83.19 | 68.58,78.11 68.58,83.19 | 66.04,78.11 66.04,83.19 | 63.5,78.11 63.5,83.19 | 60.96,78.11 60.96,83.19 | 58.42,78.11 58.42,83.19 | 55.88,78.11 55.88,83.19 | 53.34,78.11 53.34,83.19 | 50.8,78.11 50.8,83.19 | 48.26,78.11 48.26,83.19 | 45.72,78.11 45.72,83.19 | 43.18,78.11 43.18,83.19 | 40.64,78.11 40.64,83.19 | 38.1,78.11 38.1,83.19 | 35.56,78.11 35.56,83.19 | 33.02,78.11 33.02,83.19 | 30.48,78.11 30.48,83.19 | 27.94,78.11 27.94,83.19 | 25.4,78.11 25.4,83.19 | 22.86,78.11 22.86,83.19 | 20.32,78.11 20.32,83.19 | 17.78,78.11 17.78,83.19 | 15.24,78.11 15.24,83.19 | 12.7,78.11 12.7,83.19 | 10.16,78.11 10.16,83.19 | 7.62,78.11 7.62,83.19 | 5.08,78.11 5.08,83.19
S$24
  Top 1.676: 43.18,52.7 5.08,52.7
S$25
  Top 1.676: 5.08,29.85 43.18,29.85
S$26  (via drill 1 pad 1.42)
  Top 1.676: v7.62,90.81 v10.16,90.81 | v12.7,90.81 v15.24,90.81 | v17.78,90.81 v20.32,90.81 | v22.86,90.81 v25.4,90.81 | v27.94,90.81 v30.48,90.81 | v33.02,90.81 v35.56,90.81 | v83.82,90.81 v86.36,90.81 | v78.74,90.81 v81.28,90.81 | v73.66,90.81 v76.2,90.81 | v68.58,90.81 v71.12,90.81 | v63.5,90.81 v66.04,90.81 | v58.42,90.81 v60.96,90.81 | v53.34,90.81 v55.88,90.81 | v48.26,90.81 v50.8,90.81 | v43.18,90.81 v45.72,90.81 | v38.1,90.81 v40.64,90.81 | v86.36,93.34 v86.36,95.89 | v83.82,93.34 v83.82,95.89 | v81.28,93.34 v81.28,95.89 | v78.74,93.34 v78.74,95.89 | v76.2,93.34 v76.2,95.89 | v73.66,93.34 v73.66,95.89 | v71.12,93.34 v71.12,95.89 | v68.58,93.34 v68.58,95.89 | v66.04,93.34 v66.04,95.89 | v63.5,93.34 v63.5,95.89 | v60.96,93.34 v60.96,95.89 | v58.42,93.34 v58.42,95.89 | v55.88,93.34 v55.88,95.89 | v53.34,93.34 v53.34,95.89 | v50.8,93.34 v50.8,95.89 | v48.26,93.34 v48.26,95.89 | v45.72,93.34 v45.72,95.89 | v43.18,93.34 v43.18,95.89 | v40.64,93.34 v40.64,95.89 | v38.1,93.34 v38.1,95.89 | v35.56,93.34 v35.56,95.89 | v33.02,93.34 v33.02,95.89 | v30.48,93.34 v30.48,95.89 | v27.94,93.34 v27.94,95.89 | v25.4,93.34 v25.4,95.89 | v22.86,93.34 v22.86,95.89 | v20.32,93.34 v20.32,95.89 | v17.78,93.34 v17.78,95.89 | v15.24,93.34 v15.24,95.89 | v12.7,93.34 v12.7,95.89 | v10.16,93.34 v10.16,95.89 | v7.62,93.34 v7.62,95.89 | v5.08,93.34 v5.08,95.89
  Bottom 1.676: v7.62,90.81 v10.16,90.81 | v12.7,90.81 v15.24,90.81 | v17.78,90.81 v20.32,90.81 | v22.86,90.81 v25.4,90.81 | v27.94,90.81 v30.48,90.81 | v33.02,90.81 v35.56,90.81 | v83.82,90.81 v86.36,90.81 | v78.74,90.81 v81.28,90.81 | v73.66,90.81 v76.2,90.81 | v68.58,90.81 v71.12,90.81 | v63.5,90.81 v66.04,90.81 | v58.42,90.81 v60.96,90.81 | v53.34,90.81 v55.88,90.81 | v48.26,90.81 v50.8,90.81 | v43.18,90.81 v45.72,90.81 | v38.1,90.81 v40.64,90.81 | v86.36,93.34 v86.36,95.89 | v83.82,93.34 v83.82,95.89 | v81.28,93.34 v81.28,95.89 | v78.74,93.34 v78.74,95.89 | v76.2,93.34 v76.2,95.89 | v73.66,93.34 v73.66,95.89 | v71.12,93.34 v71.12,95.89 | v68.58,93.34 v68.58,95.89 | v66.04,93.34 v66.04,95.89 | v63.5,93.34 v63.5,95.89 | v60.96,93.34 v60.96,95.89 | v58.42,93.34 v58.42,95.89 | v55.88,93.34 v55.88,95.89 | v53.34,93.34 v53.34,95.89 | v50.8,93.34 v50.8,95.89 | v48.26,93.34 v48.26,95.89 | v45.72,93.34 v45.72,95.89 | v43.18,93.34 v43.18,95.89 | v40.64,93.34 v40.64,95.89 | v38.1,93.34 v38.1,95.89 | v35.56,93.34 v35.56,95.89 | v33.02,93.34 v33.02,95.89 | v30.48,93.34 v30.48,95.89 | v27.94,93.34 v27.94,95.89 | v25.4,93.34 v25.4,95.89 | v22.86,93.34 v22.86,95.89 | v20.32,93.34 v20.32,95.89 | v17.78,93.34 v17.78,95.89 | v15.24,93.34 v15.24,95.89 | v12.7,93.34 v12.7,95.89 | v10.16,93.34 v10.16,95.89 | v7.62,93.34 v7.62,95.89 | v5.08,93.34 v5.08,95.89
S$27  (via drill 1 pad 1.42)
  Top 1.676: v86.36,98.42 v86.36,100.97 | v83.82,98.42 v83.82,100.97 | v81.28,98.42 v81.28,100.97 | v78.74,98.42 v78.74,100.97 | v76.2,98.42 v76.2,100.97 | v73.66,98.42 v73.66,100.97 | v71.12,98.42 v71.12,100.97 | v68.58,98.42 v68.58,100.97 | v66.04,98.42 v66.04,100.97 | v63.5,98.42 v63.5,100.97 | v60.96,98.42 v60.96,100.97 | v58.42,98.42 v58.42,100.97 | v55.88,98.42 v55.88,100.97 | v53.34,98.42 v53.34,100.97 | v50.8,98.42 v50.8,100.97 | v48.26,98.42 v48.26,100.97 | v45.72,98.42 v45.72,100.97 | v43.18,98.42 v43.18,100.97 | v40.64,98.42 v40.64,100.97 | v38.1,98.42 v38.1,100.97 | v35.56,98.42 v35.56,100.97 | v33.02,98.42 v33.02,100.97 | v30.48,98.42 v30.48,100.97 | v27.94,98.42 v27.94,100.97 | v25.4,98.42 v25.4,100.97 | v22.86,98.42 v22.86,100.97 | v20.32,98.42 v20.32,100.97 | v17.78,98.42 v17.78,100.97 | v15.24,98.42 v15.24,100.97 | v12.7,98.42 v12.7,100.97 | v10.16,98.42 v10.16,100.97 | v7.62,98.42 v7.62,100.97 | v5.08,98.42 v5.08,100.97
  Bottom 1.676: v86.36,98.42 v86.36,100.97 | v83.82,98.42 v83.82,100.97 | v81.28,98.42 v81.28,100.97 | v78.74,98.42 v78.74,100.97 | v76.2,98.42 v76.2,100.97 | v73.66,98.42 v73.66,100.97 | v71.12,98.42 v71.12,100.97 | v68.58,98.42 v68.58,100.97 | v66.04,98.42 v66.04,100.97 | v63.5,98.42 v63.5,100.97 | v60.96,98.42 v60.96,100.97 | v58.42,98.42 v58.42,100.97 | v55.88,98.42 v55.88,100.97 | v53.34,98.42 v53.34,100.97 | v50.8,98.42 v50.8,100.97 | v48.26,98.42 v48.26,100.97 | v45.72,98.42 v45.72,100.97 | v43.18,98.42 v43.18,100.97 | v40.64,98.42 v40.64,100.97 | v38.1,98.42 v38.1,100.97 | v35.56,98.42 v35.56,100.97 | v33.02,98.42 v33.02,100.97 | v30.48,98.42 v30.48,100.97 | v27.94,98.42 v27.94,100.97 | v25.4,98.42 v25.4,100.97 | v22.86,98.42 v22.86,100.97 | v20.32,98.42 v20.32,100.97 | v17.78,98.42 v17.78,100.97 | v15.24,98.42 v15.24,100.97 | v12.7,98.42 v12.7,100.97 | v10.16,98.42 v10.16,100.97 | v7.62,98.42 v7.62,100.97 | v5.08,98.42 v5.08,100.97
S$28  (via drill 1 pad 1.42)
  Top 1.676: v86.36,103.5 v86.36,106.05 | v83.82,103.5 v83.82,106.05 | v81.28,103.5 v81.28,106.05 | v78.74,103.5 v78.74,106.05 | v76.2,103.5 v76.2,106.05 | v73.66,103.5 v73.66,106.05 | v71.12,103.5 v71.12,106.05 | v68.58,103.5 v68.58,106.05 | v66.04,103.5 v66.04,106.05 | v63.5,103.5 v63.5,106.05 | v60.96,103.5 v60.96,106.05 | v58.42,103.5 v58.42,106.05 | v55.88,103.5 v55.88,106.05 | v53.34,103.5 v53.34,106.05 | v50.8,103.5 v50.8,106.05 | v48.26,103.5 v48.26,106.05 | v45.72,103.5 v45.72,106.05 | v43.18,103.5 v43.18,106.05 | v40.64,103.5 v40.64,106.05 | v38.1,103.5 v38.1,106.05 | v35.56,103.5 v35.56,106.05 | v33.02,103.5 v33.02,106.05 | v30.48,103.5 v30.48,106.05 | v27.94,103.5 v27.94,106.05 | v25.4,103.5 v25.4,106.05 | v22.86,103.5 v22.86,106.05 | v20.32,103.5 v20.32,106.05 | v17.78,103.5 v17.78,106.05 | v15.24,103.5 v15.24,106.05 | v12.7,103.5 v12.7,106.05 | v10.16,103.5 v10.16,106.05 | v7.62,103.5 v7.62,106.05 | v5.08,103.5 v5.08,106.05
  Bottom 1.676: v86.36,103.5 v86.36,106.05 | v83.82,103.5 v83.82,106.05 | v81.28,103.5 v81.28,106.05 | v78.74,103.5 v78.74,106.05 | v76.2,103.5 v76.2,106.05 | v73.66,103.5 v73.66,106.05 | v71.12,103.5 v71.12,106.05 | v68.58,103.5 v68.58,106.05 | v66.04,103.5 v66.04,106.05 | v63.5,103.5 v63.5,106.05 | v60.96,103.5 v60.96,106.05 | v58.42,103.5 v58.42,106.05 | v55.88,103.5 v55.88,106.05 | v53.34,103.5 v53.34,106.05 | v50.8,103.5 v50.8,106.05 | v48.26,103.5 v48.26,106.05 | v45.72,103.5 v45.72,106.05 | v43.18,103.5 v43.18,106.05 | v40.64,103.5 v40.64,106.05 | v38.1,103.5 v38.1,106.05 | v35.56,103.5 v35.56,106.05 | v33.02,103.5 v33.02,106.05 | v30.48,103.5 v30.48,106.05 | v27.94,103.5 v27.94,106.05 | v25.4,103.5 v25.4,106.05 | v22.86,103.5 v22.86,106.05 | v20.32,103.5 v20.32,106.05 | v17.78,103.5 v17.78,106.05 | v15.24,103.5 v15.24,106.05 | v12.7,103.5 v12.7,106.05 | v10.16,103.5 v10.16,106.05 | v7.62,103.5 v7.62,106.05 | v5.08,103.5 v5.08,106.05
S$29
  Top 1.676: 45.72,29.85 86.36,29.85
S$30  (via drill 1 pad 1.42)
  Top 1.422: v17.78,12.06 17.78,1.27 | 20.32,12.06 20.32,1.27 | 22.86,12.06 22.86,1.27 | 25.4,12.06 25.4,1.27 | 27.94,12.06 27.94,1.27 | 30.48,12.06 30.48,1.27 | 33.02,12.06 33.02,1.27 | 35.56,12.06 35.56,1.27 | 38.1,12.06 38.1,1.27 | 40.64,12.06 40.64,1.27 | 43.18,12.06 43.18,1.27 | 45.72,12.06 45.72,1.27 | 48.26,12.06 48.26,1.27 | 50.8,12.06 50.8,1.27 | 53.34,12.06 53.34,1.27 | 55.88,12.06 55.88,1.27 | 58.42,12.06 58.42,1.27 | 60.96,12.06 60.96,1.27 | 63.5,12.06 63.5,1.27 | 66.04,12.06 66.04,1.27 | 68.58,12.06 68.58,1.27 | 71.12,12.06 71.12,1.27 | 73.66,12.06 73.66,1.27 | 76.2,12.06 76.2,1.27 | 78.74,12.06 78.74,1.27 | 81.28,12.06 81.28,1.27 | 83.82,12.06 83.82,1.27 | 86.36,12.06 86.36,1.27
S$31  (via drill 1 pad 1.42)
  other vias: 20.32,12.06
S$32  (via drill 1 pad 1.42)
  other vias: 22.86,12.06
S$33  (via drill 1 pad 1.42)
  other vias: 25.4,12.06
S$34  (via drill 1 pad 1.42)
  other vias: 33.02,12.06
S$35  (via drill 1 pad 1.42)
  other vias: 35.56,12.06
S$36  (via drill 1 pad 1.42)
  other vias: 38.1,12.06
S$37  (via drill 1 pad 1.42)
  other vias: 40.64,12.06
S$38  (via drill 1 pad 1.42)
  other vias: 43.18,12.06
S$39  (via drill 1 pad 1.42)
  other vias: 45.72,12.06
S$40  (via drill 1 pad 1.42)
  other vias: 48.26,12.06
S$41  (via drill 1 pad 1.42)
  other vias: 50.8,12.06
S$42  (via drill 1 pad 1.42)
  other vias: 53.34,12.06
S$43  (via drill 1 pad 1.42)
  other vias: 55.88,12.06
S$44  (via drill 1 pad 1.42)
  other vias: 58.42,12.06
S$45  (via drill 1 pad 1.42)
  other vias: 60.96,12.06
S$46  (via drill 1 pad 1.42)
  other vias: 63.5,12.06
S$47  (via drill 1 pad 1.42)
  other vias: 66.04,12.06
S$48  (via drill 1 pad 1.42)
  other vias: 68.58,12.06
S$49  (via drill 1 pad 1.42)
  other vias: 71.12,12.06
S$50  (via drill 1 pad 1.42)
  other vias: 73.66,12.06
S$51  (via drill 1 pad 1.42)
  other vias: 76.2,12.06
S$52  (via drill 1 pad 1.42)
  other vias: 78.74,12.06
S$53  (via drill 1 pad 1.42)
  other vias: 81.28,12.06
S$54  (via drill 1 pad 1.42)
  other vias: 83.82,12.06
S$55  (via drill 1 pad 1.42)
  other vias: 86.36,12.06
S$56  (via drill 1 pad 1.42)
  other vias: 27.94,12.06
S$57  (via drill 1 pad 1.42)
  other vias: 30.48,12.06
S$72  (via drill 1 pad 1.42)
  Top 1.676: 17.78,14.6 17.78,17.14 | 20.32,14.6 20.32,17.14 | 22.86,14.6 22.86,17.14 | 25.4,14.6 25.4,17.14 | 27.94,14.6 27.94,17.14 | 30.48,14.6 30.48,17.14 | 33.02,14.6 33.02,17.14 | 35.56,14.6 35.56,17.14 | 38.1,14.6 38.1,17.14 | 40.64,14.6 40.64,17.14 | 43.18,14.6 43.18,17.14 | 45.72,14.6 45.72,17.14 | 48.26,14.6 48.26,17.14 | 50.8,14.6 50.8,17.14 | 53.34,14.6 53.34,17.14 | 55.88,14.6 55.88,17.14 | 58.42,14.6 58.42,17.14 | 60.96,14.6 60.96,17.14 | 63.5,14.6 63.5,17.14 | 66.04,14.6 66.04,17.14 | 68.58,14.6 68.58,17.14 | 71.12,14.6 71.12,17.14 | 73.66,14.6 73.66,17.14 | 76.2,14.6 76.2,17.14 | 78.74,14.6 78.74,17.14 | 81.28,14.6 81.28,17.14 | 83.82,14.6 83.82,17.14 | 86.36,14.6 86.36,17.14 | 15.24,14.6 15.24,17.14 | 12.7,14.6 12.7,17.14 | 10.16,14.6 10.16,17.14 | 7.62,14.6 7.62,17.14 | 5.08,14.6 5.08,17.14 | v2.54,14.6 v2.54,17.14
  Bottom 0.305: 53.34,9.53 54.61,10.79 54.61,13.33 53.34,14.6 | 50.8,9.53 52.07,10.79 52.07,13.33 50.8,14.6 | 48.26,9.53 49.53,10.79 49.53,13.33 48.26,14.6 | 45.72,9.53 46.99,10.79 46.99,13.33 45.72,14.6 | 43.18,9.53 44.45,10.79 44.45,13.33 43.18,14.6 | 40.64,9.53 41.91,10.79 41.91,13.33 40.64,14.6 | 38.1,9.53 39.37,10.79 39.37,13.33 38.1,14.6 | 35.56,9.53 36.83,10.79 36.83,13.33 35.56,14.6 | 30.48,9.53 31.75,10.79 31.75,13.33 30.48,14.6 | 27.94,9.53 29.21,10.79 29.21,13.33 27.94,14.6 | 25.4,9.53 26.67,10.79 26.67,13.33 25.4,14.6 | 22.86,9.53 24.13,10.79 24.13,13.33 22.86,14.6 | 20.32,9.53 21.59,10.79 21.59,13.33 20.32,14.6 | 17.78,9.53 19.05,10.79 19.05,13.33 17.78,14.6 | 33.02,14.6 34.29,13.33 34.29,10.79 33.02,9.53 | 55.88,9.53 57.15,10.79 57.15,13.33 55.88,14.6 | 58.42,9.53 59.69,10.79 59.69,13.33 58.42,14.6 | 60.96,9.53 62.23,10.79 62.23,13.33 60.96,14.6 | 63.5,9.53 64.77,10.79 64.77,13.33 63.5,14.6 | 66.04,9.53 67.31,10.79 67.31,13.33 66.04,14.6 | 68.58,9.53 69.85,10.79 69.85,13.33 68.58,14.6 | 71.12,9.53 72.39,10.79 72.39,13.33 71.12,14.6 | 73.66,9.53 74.93,10.79 74.93,13.33 73.66,14.6 | 76.2,9.53 77.47,10.79 77.47,13.33 76.2,14.6 | 78.74,9.53 80.01,10.79 80.01,13.33 78.74,14.6 | 81.28,9.53 82.55,10.79 82.55,13.33 81.28,14.6 | 83.82,9.53 85.09,10.79 85.09,13.33 83.82,14.6 | 86.36,9.53 87.63,10.79 87.63,13.33 86.36,14.6
  Bottom 1.422: 53.34,1.27 53.34,9.53 | 55.88,1.27 55.88,9.53 | 58.42,1.27 58.42,9.53 | 60.96,1.27 60.96,9.53 | 63.5,1.27 63.5,9.53 | 66.04,1.27 66.04,9.53 | 68.58,1.27 68.58,9.53 | 71.12,1.27 71.12,9.53 | 73.66,1.27 73.66,9.53 | 76.2,1.27 76.2,9.53 | 78.74,1.27 78.74,9.53 | 81.28,1.27 81.28,9.53 | 83.82,1.27 83.82,9.53 | 86.36,1.27 86.36,9.53 | 50.8,1.27 50.8,9.53 | 48.26,1.27 48.26,9.53 | 45.72,1.27 45.72,9.53 | 43.18,1.27 43.18,9.53 | 40.64,1.27 40.64,9.53 | 38.1,1.27 38.1,9.53 | 35.56,1.27 35.56,9.53 | 30.48,1.27 30.48,9.53 | 27.94,1.27 27.94,9.53 | 25.4,1.27 25.4,9.53 | 22.86,9.53 22.86,1.27 | 20.32,1.27 20.32,9.53 | 17.78,1.27 17.78,9.53 | 33.02,1.27 33.02,9.53
  Bottom 1.676: 17.78,14.6 17.78,17.14 | 20.32,14.6 20.32,17.14 | 22.86,14.6 22.86,17.14 | 25.4,14.6 25.4,17.14 | 27.94,14.6 27.94,17.14 | 30.48,14.6 30.48,17.14 | 33.02,14.6 33.02,17.14 | 35.56,14.6 35.56,17.14 | 38.1,14.6 38.1,17.14 | 40.64,14.6 40.64,17.14 | 43.18,14.6 43.18,17.14 | 45.72,14.6 45.72,17.14 | 48.26,14.6 48.26,17.14 | 50.8,14.6 50.8,17.14 | 53.34,14.6 53.34,17.14 | 55.88,14.6 55.88,17.14 | 58.42,14.6 58.42,17.14 | 60.96,14.6 60.96,17.14 | 63.5,14.6 63.5,17.14 | 66.04,14.6 66.04,17.14 | 68.58,14.6 68.58,17.14 | 71.12,14.6 71.12,17.14 | 73.66,14.6 73.66,17.14 | 76.2,14.6 76.2,17.14 | 78.74,14.6 78.74,17.14 | 81.28,14.6 81.28,17.14 | 83.82,14.6 83.82,17.14 | 86.36,14.6 86.36,17.14 | 15.24,14.6 15.24,17.14 | 12.7,14.6 12.7,17.14 | 10.16,14.6 10.16,17.14 | 7.62,14.6 7.62,17.14 | 5.08,14.6 5.08,17.14 | v2.54,14.6 v2.54,17.14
